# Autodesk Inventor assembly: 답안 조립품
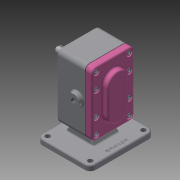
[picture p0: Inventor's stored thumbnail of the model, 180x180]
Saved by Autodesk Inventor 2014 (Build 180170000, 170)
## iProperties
Created: 2020-04
Part Number: 답안 조립품
Document SubType Name: Assembly
Designer: kh
Author: kh
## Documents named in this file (11)
- C:\Users\kh\Desktop\700407V1017\답안 조립품.iam
- C:\Users\kh\Desktop\700407V1017\1.본체.ipt
- C:\Users\kh\Desktop\700407V1017\개스킷.ipt
- C:\Users\kh\Desktop\700407V1017\메인축.ipt
- C:\Users\kh\Desktop\700407V1017\베어링부시.ipt
- C:\Users\kh\Desktop\700407V1017\볼트 M5.ipt
- C:\Users\kh\Desktop\700407V1017\서브축.ipt
- C:\Users\kh\Desktop\700407V1017\스퍼기어.ipt
- C:\Users\kh\Desktop\700407V1017\오일 실 16 28 7.ipt
- C:\Users\kh\Desktop\700407V1017\커버.ipt
- C:\Users\kh\Desktop\700407V1017\키 6 x 6 x 18.ipt
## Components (2 placed, 2 different names)
1. 1.본체:1 — 각도:1, 각도:2, 각도:3, 각도:4, 각도:5, 각도:6, 각도:7, 각도:8, 각도:9, DRIVE
2. 개스킷:1 — 플러쉬:1, 플러쉬:2
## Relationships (12: Angle 10, Flush 2)
- 플러쉬:1 [Flush]: 개스킷:1
- 플러쉬:2 [Flush]: 개스킷:1
- 각도:1 [Angle]: 1.본체:1
- 각도:2 [Angle]: 1.본체:1
- 각도:3 [Angle]: 1.본체:1
- 각도:4 [Angle]: 1.본체:1
- 각도:5 [Angle]: 1.본체:1
- 각도:6 [Angle]: 1.본체:1
- 각도:7 [Angle]: 1.본체:1
- 각도:8 [Angle]: 1.본체:1
- 각도:9 [Angle]: 1.본체:1
- DRIVE [Angle]: 1.본체:1
